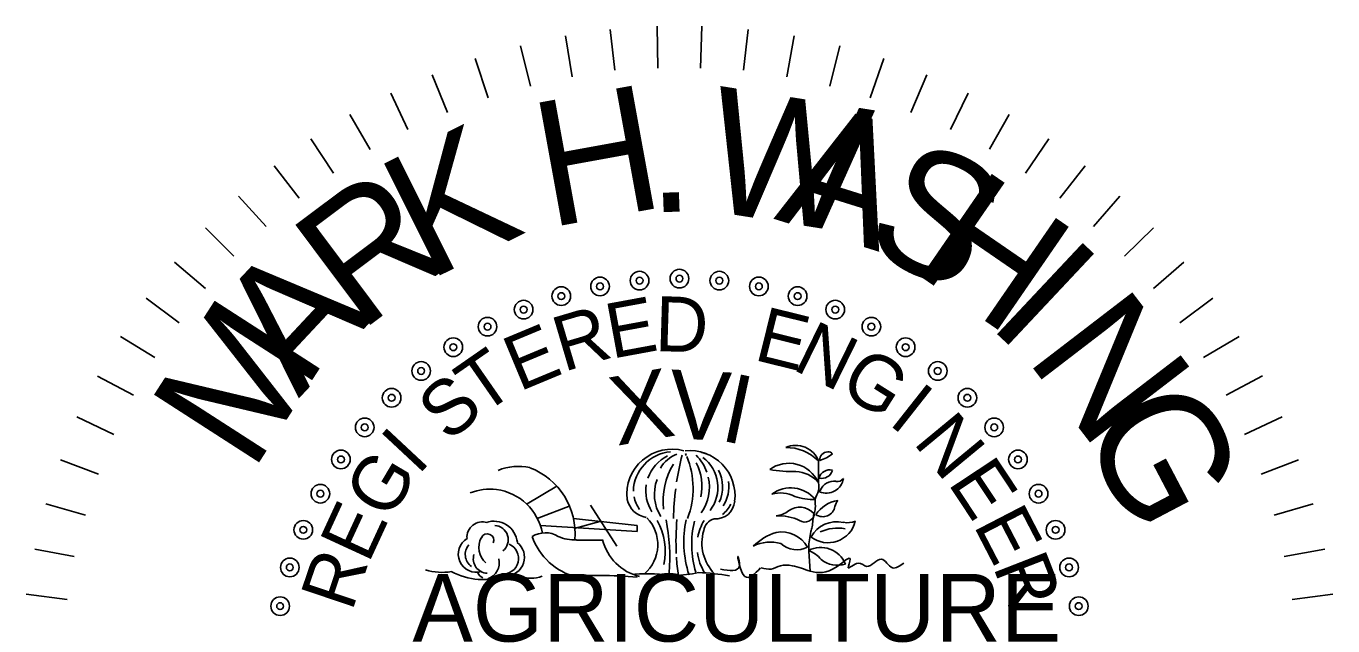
# Model space of a CAD drawing. Extents: x 1623795.1 to 1623879, y 427353.8 to 427391.8.
# Drawn here: x 1623877.016 to 1623878.975, y 427372.297 to 427373.197 of the extents above; entities that cross this region are included whole.
import ezdxf

# ---------------------------------------------------------------- set-up
doc = ezdxf.new("R2010")
doc.units = 0
doc.layers.add('DESIGN - SHEET - Corner Text', color=7, linetype='Continuous')

msp = doc.modelspace()

# ---------------------------------------------------------------- linework, layer by layer
at = {"layer": 'DESIGN - SHEET - Corner Text'}
for p, q in [((1623877.8986, 427373.1307), (1623877.8917, 427373.192)), ((1623877.9628, 427373.1336), (1623877.9619, 427373.1969)), ((1623878.0271, 427373.1336), (1623878.0291, 427373.1969)), ((1623878.0914, 427373.1307), (1623878.0983, 427373.192)), ((1623877.8343, 427373.1208), (1623877.8245, 427373.1821)), ((1623878.1566, 427373.1208), (1623878.1675, 427373.1821)), ((1623877.7721, 427373.1069), (1623877.7572, 427373.1672)), ((1623878.2209, 427373.1069), (1623878.2357, 427373.1672)), ((1623877.7088, 427373.0892), (1623877.689, 427373.1485)), ((1623878.2812, 427373.0892), (1623878.3019, 427373.1485)), ((1623877.6475, 427373.0674), (1623877.6247, 427373.1237)), ((1623878.3425, 427373.0674), (1623878.3662, 427373.1237)), ((1623877.5882, 427373.0417), (1623877.5625, 427373.0961)), ((1623878.4018, 427373.0417), (1623878.4285, 427373.0961)), ((1623877.5318, 427373.012), (1623877.5012, 427373.0644)), ((1623878.4601, 427373.0121), (1623878.4898, 427373.0644)), ((1623877.4765, 427372.9765), (1623877.4429, 427373.0279)), ((1623878.5145, 427372.9764), (1623878.5491, 427373.0279)), ((1623877.4251, 427372.9389), (1623877.3875, 427372.9873)), ((1623878.5659, 427372.9389), (1623878.6035, 427372.9873)), ((1623877.3756, 427372.8964), (1623877.3341, 427372.9418)), ((1623878.6163, 427372.8964), (1623878.6558, 427372.9418)), ((1623877.3272, 427372.8519), (1623877.2847, 427372.8944)), ((1623878.6628, 427372.8519), (1623878.7063, 427372.8944)), ((1623877.2847, 427372.8034), (1623877.2382, 427372.843)), ((1623878.7062, 427372.8034), (1623878.7517, 427372.843)), ((1623877.2451, 427372.752), (1623877.1957, 427372.7886)), ((1623878.7458, 427372.752), (1623878.7952, 427372.7886)), ((1623877.2086, 427372.6997), (1623877.1572, 427372.7313)), ((1623878.7814, 427372.6996), (1623878.8347, 427372.7313)), ((1623877.1769, 427372.6433), (1623877.1226, 427372.6719)), ((1623878.815, 427372.6433), (1623878.8694, 427372.672)), ((1623877.1473, 427372.584), (1623877.0919, 427372.6107)), ((1623878.8427, 427372.584), (1623878.899, 427372.6107)), ((1623877.1245, 427372.5246), (1623877.0672, 427372.5464)), ((1623878.8674, 427372.5247), (1623878.9237, 427372.5464)), ((1623877.7671, 427372.4802), (1623877.8116, 427372.5069)), ((1623877.1048, 427372.4634), (1623877.0454, 427372.4802)), ((1623877.7819, 427372.4584), (1623877.8314, 427372.4772)), ((1623877.862, 427372.4782), (1623877.9015, 427372.4169)), ((1623878.8872, 427372.4634), (1623878.9455, 427372.4802)), ((1623877.7869, 427372.4475), (1623877.9322, 427372.4387)), ((1623877.9322, 427372.4475), (1623877.8363, 427372.4584)), ((1623877.8393, 427372.4436), (1623877.8758, 427372.4535)), ((1623877.9322, 427372.4387), (1623877.9322, 427372.4475)), ((1623877.8412, 427372.4258), (1623877.8808, 427372.4258)), ((1623877.0879, 427372.4011), (1623877.0287, 427372.412)), ((1623878.1892, 427372.409), (1623878.1912, 427372.3794)), ((1623878.902, 427372.4011), (1623878.9633, 427372.412)), ((1623877.0771, 427372.3368), (1623877.0158, 427372.3447)), ((1623878.9139, 427372.3368), (1623878.9751, 427372.3447))]:
    msp.add_line(p, q, dxfattribs=at)
for centre, radius in [((1623877.8763, 427372.8064), 0.014), ((1623877.9356, 427372.8151), 0.014), ((1623877.9356, 427372.8151), 0.00515), ((1623877.9954, 427372.8181), 0.014), ((1623877.9954, 427372.8181), 0.00515), ((1623878.0552, 427372.8151), 0.014), ((1623878.0552, 427372.8151), 0.00515), ((1623878.1145, 427372.8064), 0.014), ((1623877.8182, 427372.7918), 0.014), ((1623877.8182, 427372.7918), 0.00515), ((1623877.8763, 427372.8064), 0.00515), ((1623878.1145, 427372.8064), 0.00515), ((1623878.1726, 427372.7918), 0.014), ((1623878.1726, 427372.7918), 0.00515), ((1623877.7618, 427372.7716), 0.014), ((1623877.7618, 427372.7716), 0.00515), ((1623878.229, 427372.7716), 0.014), ((1623878.229, 427372.7716), 0.00515), ((1623877.7076, 427372.746), 0.014), ((1623878.2832, 427372.746), 0.014), ((1623877.7076, 427372.746), 0.00515), ((1623878.2832, 427372.746), 0.00515), ((1623877.6563, 427372.7152), 0.014), ((1623877.6563, 427372.7152), 0.00515), ((1623878.3345, 427372.7152), 0.014), ((1623878.3345, 427372.7152), 0.00515), ((1623877.6081, 427372.6795), 0.014), ((1623877.6081, 427372.6795), 0.00515), ((1623878.3827, 427372.6795), 0.014), ((1623878.3827, 427372.6795), 0.00515), ((1623877.5638, 427372.6393), 0.014), ((1623877.5638, 427372.6393), 0.00515), ((1623878.4271, 427372.6393), 0.014), ((1623878.4271, 427372.6393), 0.00515), ((1623877.5235, 427372.5949), 0.014), ((1623878.4673, 427372.5949), 0.014), ((1623877.5235, 427372.5949), 0.00515), ((1623878.4673, 427372.5949), 0.00515), ((1623877.4878, 427372.5468), 0.014), ((1623877.4878, 427372.5468), 0.00515), ((1623878.503, 427372.5468), 0.014), ((1623878.503, 427372.5468), 0.00515), ((1623877.457, 427372.4954), 0.014), ((1623878.5338, 427372.4954), 0.014), ((1623877.457, 427372.4954), 0.00515), ((1623878.5338, 427372.4954), 0.00515), ((1623877.4314, 427372.4412), 0.014), ((1623877.4314, 427372.4412), 0.00515), ((1623878.5594, 427372.4412), 0.014), ((1623878.5594, 427372.4412), 0.00515), ((1623877.4112, 427372.3848), 0.014), ((1623877.4112, 427372.3848), 0.00515), ((1623878.5796, 427372.3848), 0.014), ((1623878.5796, 427372.3848), 0.00515), ((1623877.3967, 427372.3267), 0.014), ((1623877.3967, 427372.3267), 0.00515), ((1623878.5941, 427372.3267), 0.014), ((1623878.5941, 427372.3267), 0.00515)]:
    msp.add_circle(centre, radius, dxfattribs=at)
for centre, radius, start, end in [((1623877.9845, 427372.4941), 0.0681, 75.025, 186.0477), ((1623878.1697, 427372.531), 0.0369, 20.377, 113.904), ((1623878.1556, 427372.4969), 0.0678, 44.8067, 90.7108), ((1623877.987, 427372.4978), 0.0607, 94.7646, 178.6363), ((1623878.0036, 427372.4997), 0.0586, 116.5204, 161.0111), ((1623878.0098, 427372.5087), 0.0497, 111.4611, 149.8752), ((1623878.4311, 427372.4458), 0.445, 166.0262, 171.3044), ((1623878.011, 427372.4923), 0.0677, 352.9456, 95.8285), ((1623877.8895, 427372.5031), 0.1264, 23.231, 24.6687), ((1623877.8895, 427372.5031), 0.1264, 339.2679, 22.415), ((1623877.9729, 427372.5053), 0.0674, 19.5835, 45.2306), ((1623877.9559, 427372.5069), 0.0733, 347.0416, 28.3993), ((1623878.0173, 427372.5063), 0.0523, 63.2331, 77.4163), ((1623877.9965, 427372.5048), 0.0565, 322.496, 52.9152), ((1623878.2184, 427372.5455), 0.0127, 92.3181, 181.8886), ((1623878.1817, 427372.6137), 0.0728, 289.3524, 306.6194), ((1623878.2186, 427372.5493), 0.00888, 42.9108, 94.1848), ((1623877.7539, 427372.4551), 0.0812, 77.8764, 111.9208), ((1623877.7336, 427372.4361), 0.1052, 354.6055, 69.198), ((1623878.0777, 427372.4845), 0.1067, 148.7487, 186.5744), ((1623878.0045, 427372.5059), 0.0556, 335.2034, 26.7159), ((1623878.1592, 427372.492), 0.049, 24.9651, 125.52), ((1623878.1612, 427372.6702), 0.1416, 257.5618, 273.5613), ((1623878.1669, 427372.4794), 0.0495, 42.2018, 86.4765), ((1623878.2204, 427372.515), 0.0161, 74.3802, 165.6605), ((1623878.2088, 427372.535), 0.0166, 256.0714, 343.9693), ((1623877.7126, 427372.4131), 0.0891, 84.4476, 110.2502), ((1623878.0036, 427372.4997), 0.0586, 171.3047, 212.2989), ((1623878.0214, 427372.4944), 0.0635, 159.6617, 211.6504), ((1623878.4311, 427372.4458), 0.445, 172.6332, 178.3879), ((1623877.9729, 427372.5053), 0.0674, 325.0081, 12.8116), ((1623878.0173, 427372.5063), 0.0523, 326.0945, 8.3007), ((1623878.1623, 427372.4575), 0.0467, 38.357, 127.4175), ((1623878.2157, 427372.522), 0.0258, 246.6168, 351.6849), ((1623878.2276, 427372.4908), 0.0233, 84.0806, 155.5598), ((1623878.2323, 427372.5246), 0.0109, 257.6292, 324.7162), ((1623877.7097, 427372.4208), 0.0818, 11.0098, 81.9084), ((1623877.9509, 427372.494), 0.0346, 191.8694, 261.3544), ((1623877.9754, 427372.501), 0.0492, 191.9249, 216.1971), ((1623878.0495, 427372.4863), 0.0288, 265.7144, 355.3888), ((1623878.1469, 427372.4499), 0.0466, 62.4897, 106.2201), ((1623878.1993, 427372.5903), 0.1038, 252.6921, 269.7755), ((1623878.2426, 427372.4338), 0.0525, 100.7567, 144.5997), ((1623878.2356, 427372.4803), 0.0355, 145.9052, 149.5502), ((1623878.2691, 427372.4623), 0.043, 147.5707, 160.9356), ((1623878.0361, 427372.4968), 0.0401, 306.1094, 334.6375), ((1623878.1388, 427372.4928), 0.0305, 273.1132, 310.9858), ((1623878.1755, 427372.4465), 0.0286, 42.9746, 125.6918), ((1623878.1835, 427372.4678), 0.0149, 238.097, 349.3695), ((1623878.2103, 427372.4794), 0.0185, 235.7604, 350.205), ((1623877.6998, 427372.4301), 0.023, 71.8287, 184.9372), ((1623877.717, 427372.4185), 0.0357, 6.3907, 108.5764), ((1623877.7173, 427372.4264), 0.0214, 308.3309, 87.1915), ((1623877.9048, 427372.419), 0.0581, 310.9736, 43.9833), ((1623877.8808, 427372.4091), 0.0933, 347.7846, 29.4879), ((1623877.6993, 427372.4014), 0.2815, 355.0093, 11.22), ((1623878.36, 427372.4235), 0.3698, 174.8376, 182.7584), ((1623878.1641, 427372.4237), 0.1622, 168.3813, 197.8921), ((1623878.1633, 427372.4198), 0.1495, 166.7019, 196.3347), ((1623878.0978, 427372.4168), 0.076, 149.5268, 169.8408), ((1623878.0527, 427372.4371), 0.0211, 104.6932, 172.2979), ((1623878.144, 427372.3898), 0.0726, 64.1859, 92.8154), ((1623878.2181, 427372.4641), 0.0422, 232.7702, 346.3113), ((1623878.2316, 427372.4091), 0.0444, 77.4745, 151.2427), ((1623878.2331, 427372.3787), 0.0651, 80.6317, 114.0718), ((1623878.2473, 427372.4855), 0.0336, 259.6005, 290.6212), ((1623877.6912, 427372.4048), 0.0274, 121.3738, 285.9536), ((1623877.7268, 427372.4148), 0.032, 152.9085, 226.7504), ((1623877.7073, 427372.4254), 0.00975, 337.0132, 156.1324), ((1623877.7942, 427372.4002), 0.0366, 58.3194, 122.3154), ((1623877.8638, 427372.462), 0.0944, 199.055, 255.9221), ((1623877.8368, 427372.48), 0.0539, 244.3801, 274.5673), ((1623877.9532, 427372.4445), 0.0753, 194.0581, 256.2692), ((1623878.0951, 427372.4215), 0.066, 163.7573, 224.6566), ((1623878.1665, 427372.355), 0.0864, 107.5902, 134.3196), ((1623878.1479, 427372.3922), 0.0458, 30.2843, 99.3981), ((1623877.6966, 427372.4044), 0.0224, 140.0601, 233.8347), ((1623877.731, 427372.3982), 0.0232, 264.078, 67.2244), ((1623877.7356, 427372.3999), 0.0275, 270.0423, 53.2946), ((1623878.0978, 427372.4168), 0.076, 187.4456, 211.6883), ((1623878.1319, 427372.3632), 0.0595, 74.7022, 115.6176), ((1623878.1713, 427372.4467), 0.0353, 227.7265, 297.2033), ((1623878.2073, 427372.375), 0.0398, 21.7586, 117.5504), ((1623878.1743, 427372.37), 0.0428, 38.3904, 70.0715), ((1623877.7078, 427372.3976), 0.0215, 162.6361, 267.6297), ((1623877.7002, 427372.3916), 0.025, 287.8506, 14.3765), ((1623878.36, 427372.4235), 0.3698, 183.5862, 187.8812), ((1623878.2324, 427372.4269), 0.039, 230.9083, 287.7233), ((1623877.6393, 427372.4644), 0.087, 253.511, 279.4998), ((1623877.7016, 427372.4693), 0.1027, 241.9612, 289.3361), ((1623877.7057, 427372.3814), 0.0133, 197.4636, 248.2943), ((1623877.7454, 427372.398), 0.0274, 249.1271, 292.5616), ((1623877.7737, 427372.4088), 0.0403, 243.7711, 293.1854), ((1623877.8742, 427371.7821), 0.5907, 84.3612, 95.2382), ((1623877.9469, 427372.0507), 0.3246, 82.7319, 93.3154), ((1623877.9875, 427372.5228), 0.15, 270.1752, 284.1035), ((1623877.9936, 427371.8688), 0.5094, 81.3274, 86.5721)]:
    msp.add_arc(centre, radius, start, end, dxfattribs=at)
for points in [[(1623878.204, 427372.5444), (1623878.2041, 427372.5345), (1623878.2041, 427372.5128), (1623878.2041, 427372.5118)], [(1623878.2041, 427372.5118), (1623878.2041, 427372.5), (1623878.1991, 427372.4871), (1623878.1991, 427372.4733), (1623878.1971, 427372.4653), (1623878.1942, 427372.4456), (1623878.1922, 427372.4387)], [(1623878.1922, 427372.4387), (1623878.1892, 427372.4139), (1623878.1892, 427372.409)], [(1623878.0568, 427372.3823), (1623878.0854, 427372.3873), (1623878.0834, 427372.4011), (1623878.0933, 427372.3714), (1623878.1171, 427372.3843)], [(1623878.1181, 427372.3843), (1623878.1329, 427372.3823), (1623878.1467, 427372.3873), (1623878.1645, 427372.3873), (1623878.1912, 427372.3794), (1623878.2317, 427372.3862), (1623878.2515, 427372.3971), (1623878.2485, 427372.3843), (1623878.2634, 427372.3912), (1623878.2762, 427372.3863), (1623878.298, 427372.3972), (1623878.3148, 427372.3843), (1623878.3316, 427372.3912)]]:
    msp.add_spline(points, degree=3, dxfattribs=at)

# ---------------------------------------------------------------- texts
for s, height, rotation, p in [('H', 0.1875, 10.3203, (1623877.7991, 427372.8942)), ('W', 0.1875, 351.0345, (1623878.0265, 427372.922)), ('A', 0.1875, 342.6168, (1623878.1358, 427372.9081)), ('K', 0.1875, 26.4955, (1623877.6179, 427372.8137)), ('S', 0.1875, 333.9015, (1623878.2654, 427372.8664)), ('H', 0.1875, 325.4678, (1623878.3405, 427372.8324)), ('R', 0.1875, 36.8106, (1623877.5154, 427372.7363)), ('.', 0.1875, 2.0597, (1623877.9489, 427372.917)), ('I', 0.1875, 316.8235, (1623878.4548, 427372.7506)), ('A', 0.1875, 46.9413, (1623877.4244, 427372.6379)), ('N', 0.1875, 307.5096, (1623878.5132, 427372.6996)), ('M', 0.1875, 57.1889, (1623877.354, 427372.5251)), ('E', 0.0825, 10.4494, (1623877.8936, 427372.6977)), ('D', 0.0825, 358.2737, (1623877.9579, 427372.7095)), ('R', 0.0825, 16.5372, (1623877.8215, 427372.6779)), ('E', 0.0825, 346.098, (1623878.1052, 427372.6967)), ('E', 0.0825, 22.625, (1623877.7552, 427372.6482)), ('N', 0.0825, 333.9223, (1623878.1626, 427372.6828)), ('T', 0.0825, 34.8007, (1623877.6989, 427372.6117)), ('G', 0.0825, 327.8345, (1623878.2317, 427372.6502)), ('X', 0.103, 10.0002, (1623877.9015, 427372.5672)), ('V', 0.103, 357.0002, (1623877.9777, 427372.579)), ('S', 0.0825, 40.8886, (1623877.6495, 427372.5711)), ('I', 0.103, 347.9994, (1623878.0538, 427372.5761)), ('I', 0.0825, 321.7466, (1623878.3069, 427372.6008)), ('G', 0.1875, 297.7033, (1623878.5938, 427372.596)), ('N', 0.0825, 309.571, (1623878.3445, 427372.5721)), ('I', 0.0825, 46.9764, (1623877.603, 427372.5217)), ('G', 0.0825, 59.1521, (1623877.5605, 427372.4535)), ('E', 0.0825, 303.4831, (1623878.3968, 427372.5118)), ('E', 0.0825, 65.2399, (1623877.5289, 427372.3892)), ('E', 0.0825, 297.3953, (1623878.4354, 427372.4486)), ('R', 0.0825, 71.3278, (1623877.5042, 427372.3171)), ('R', 0.0825, 291.3074, (1623878.465, 427372.3862))]:
    msp.add_text(s, height=height, rotation=rotation, dxfattribs=at).set_placement(p)
msp.add_text('AGRICULTURE', height=0.101481, dxfattribs=at).set_placement((1623877.5951, 427372.2736))

doc.saveas('drawing.dxf')
